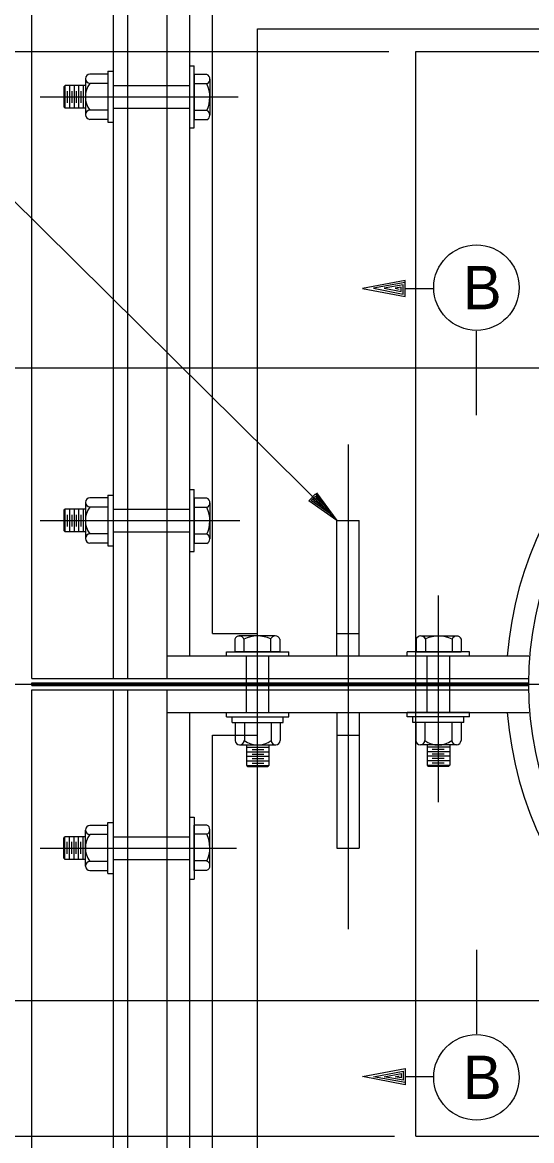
# Model space of a CAD drawing. Extents: x 22369.6 to 22389.4, y 22369.6 to 22386.
# Drawn here: x 22372.155 to 22373.095, y 22377.472 to 22379.534 of the extents above; entities that cross this region are included whole.
import ezdxf

# ---------------------------------------------------------------- set-up
doc = ezdxf.new("R2010")
doc.units = 0
for name, color, linetype in [('Level 1', 7, 'Continuous'), ('Level 2', 7, 'Continuous'), ('Level 3', 7, 'Continuous')]:
    doc.layers.add(name, color=color, linetype=linetype)

msp = doc.modelspace()

# ---------------------------------------------------------------- linework, layer by layer
at = {"layer": 'Level 1'}
for p, q in [((22370.551, 22379.4805), (22372.831, 22379.4805)), ((22372.4643, 22379.4545), (22372.4721, 22379.4545)), ((22372.4721, 22379.3399), (22372.4721, 22379.4545)), ((22372.3132, 22379.4389), (22372.28, 22379.4389)), ((22372.3132, 22379.4441), (22372.3132, 22379.3503)), ((22372.3132, 22379.4441), (22372.3237, 22379.4441)), ((22372.4721, 22379.4382), (22372.4721, 22379.3549)), ((22372.4956, 22379.4382), (22372.4721, 22379.4382)), ((22372.2341, 22379.418), (22372.232, 22379.4158)), ((22372.232, 22379.4158), (22372.232, 22379.3785)), ((22372.234, 22379.418), (22372.234, 22379.3764)), ((22372.2716, 22379.418), (22372.2341, 22379.418)), ((22372.2424, 22379.418), (22372.2424, 22379.3764)), ((22372.2507, 22379.418), (22372.2507, 22379.3764)), ((22372.259, 22379.418), (22372.259, 22379.3764)), ((22372.2674, 22379.418), (22372.2674, 22379.3764)), ((22372.2716, 22379.4304), (22372.2716, 22379.3639)), ((22372.3132, 22379.4217), (22372.28, 22379.4217)), ((22372.3237, 22379.418), (22372.4643, 22379.418)), ((22372.4958, 22379.421), (22372.4721, 22379.421)), ((22372.5012, 22379.4297), (22372.5012, 22379.3633)), ((22372.188, 22379.3972), (22372.5534, 22379.3972)), ((22372.2382, 22379.4076), (22372.2382, 22379.3858)), ((22372.2465, 22379.4076), (22372.2465, 22379.3858)), ((22372.2549, 22379.4076), (22372.2549, 22379.3858)), ((22372.2632, 22379.4076), (22372.2632, 22379.3858)), ((22372.2343, 22379.3764), (22372.232, 22379.3785)), ((22372.2716, 22379.3764), (22372.2343, 22379.3764)), ((22372.3132, 22379.3724), (22372.28, 22379.3724)), ((22372.3237, 22379.3764), (22372.4643, 22379.3764)), ((22372.4957, 22379.3717), (22372.4721, 22379.3717)), ((22372.3132, 22379.3555), (22372.28, 22379.3555)), ((22372.28, 22379.3555), (22372.28, 22379.3555)), ((22372.3132, 22379.3503), (22372.3237, 22379.3503)), ((22372.4956, 22379.3549), (22372.4721, 22379.3549)), ((22372.4643, 22379.3399), (22372.4721, 22379.3399)), ((22370.7204, 22378.8972), (22373.7143, 22378.8972)), ((22372.756, 22378.7557), (22372.756, 22377.8621)), ((22372.4643, 22378.6732), (22372.4721, 22378.6732)), ((22372.4721, 22378.5587), (22372.4721, 22378.6732)), ((22372.2716, 22378.6491), (22372.2716, 22378.5827)), ((22372.3132, 22378.6576), (22372.28, 22378.6576)), ((22372.3132, 22378.6628), (22372.3132, 22378.5691)), ((22372.3132, 22378.6628), (22372.3237, 22378.6628)), ((22372.4721, 22378.657), (22372.4721, 22378.5737)), ((22372.4956, 22378.657), (22372.4721, 22378.657)), ((22372.5012, 22378.6485), (22372.5012, 22378.582)), ((22372.2341, 22378.6368), (22372.232, 22378.6346)), ((22372.232, 22378.6346), (22372.232, 22378.5972)), ((22372.234, 22378.6368), (22372.234, 22378.5951)), ((22372.2716, 22378.6368), (22372.2341, 22378.6368)), ((22372.2424, 22378.6368), (22372.2424, 22378.5951)), ((22372.2507, 22378.6368), (22372.2507, 22378.5951)), ((22372.259, 22378.6368), (22372.259, 22378.5951)), ((22372.2674, 22378.6368), (22372.2674, 22378.5951)), ((22372.3132, 22378.6404), (22372.28, 22378.6404)), ((22372.3237, 22378.6368), (22372.4643, 22378.6368)), ((22372.4958, 22378.6398), (22372.4721, 22378.6398)), ((22372.188, 22378.616), (22372.5565, 22378.616)), ((22372.2382, 22378.6263), (22372.2382, 22378.6045)), ((22372.2465, 22378.6263), (22372.2465, 22378.6045)), ((22372.2549, 22378.6263), (22372.2549, 22378.6045)), ((22372.2632, 22378.6263), (22372.2632, 22378.6045)), ((22372.2343, 22378.5951), (22372.232, 22378.5972)), ((22372.2716, 22378.5951), (22372.2343, 22378.5951)), ((22372.3132, 22378.5911), (22372.28, 22378.5911)), ((22372.3237, 22378.5951), (22372.4643, 22378.5951)), ((22372.4957, 22378.5905), (22372.4721, 22378.5905)), ((22372.3132, 22378.5743), (22372.28, 22378.5743)), ((22372.28, 22378.5743), (22372.28, 22378.5743)), ((22372.3132, 22378.5691), (22372.3237, 22378.5691)), ((22372.4956, 22378.5737), (22372.4721, 22378.5737)), ((22372.4643, 22378.5587), (22372.4721, 22378.5587)), ((22372.5893, 22378.0966), (22372.5893, 22378.4775)), ((22372.9226, 22378.0966), (22372.9226, 22378.4775)), ((22372.6218, 22378.4029), (22372.5554, 22378.4029)), ((22372.8901, 22378.4029), (22372.9566, 22378.4029)), ((22372.547, 22378.3973), (22372.547, 22378.3738)), ((22372.5638, 22378.3974), (22372.5638, 22378.3738)), ((22372.6131, 22378.3975), (22372.6131, 22378.3738)), ((22372.6303, 22378.3973), (22372.6303, 22378.3738)), ((22372.8816, 22378.3973), (22372.8816, 22378.3738)), ((22372.8988, 22378.3975), (22372.8988, 22378.3738)), ((22372.9481, 22378.3974), (22372.9481, 22378.3738)), ((22372.9649, 22378.3973), (22372.9649, 22378.3738)), ((22372.532, 22378.3738), (22372.6466, 22378.3738)), ((22372.532, 22378.366), (22372.532, 22378.3738)), ((22372.6303, 22378.3738), (22372.547, 22378.3738)), ((22372.5685, 22378.2618), (22372.5685, 22378.366)), ((22372.6101, 22378.2618), (22372.6101, 22378.366)), ((22372.6466, 22378.366), (22372.6466, 22378.3738)), ((22372.9799, 22378.3738), (22372.8653, 22378.3738)), ((22372.8653, 22378.366), (22372.8653, 22378.3738)), ((22372.8816, 22378.3738), (22372.9649, 22378.3738)), ((22372.9018, 22378.2618), (22372.9018, 22378.366)), ((22372.9435, 22378.2618), (22372.9435, 22378.366)), ((22372.9799, 22378.366), (22372.9799, 22378.3738)), ((22371.1298, 22378.3139), (22373.7143, 22378.3139)), ((22372.1726, 22378.3165), (22373.0893, 22378.3165)), ((22372.1726, 22378.3113), (22372.1726, 22378.3165)), ((22372.1726, 22378.3113), (22373.0893, 22378.3113)), ((22372.532, 22378.254), (22372.532, 22378.2618)), ((22372.532, 22378.2618), (22372.6466, 22378.2618)), ((22372.6466, 22378.254), (22372.6466, 22378.2618)), ((22372.8653, 22378.254), (22372.8653, 22378.2618)), ((22372.9799, 22378.2618), (22372.8653, 22378.2618)), ((22372.9799, 22378.254), (22372.9799, 22378.2618)), ((22372.532, 22378.254), (22372.6466, 22378.254)), ((22372.5424, 22378.2436), (22372.5424, 22378.254)), ((22372.5424, 22378.2436), (22372.6362, 22378.2436)), ((22372.5476, 22378.2436), (22372.5476, 22378.2103)), ((22372.5648, 22378.2436), (22372.5648, 22378.2103)), ((22372.6141, 22378.2436), (22372.6141, 22378.2103)), ((22372.631, 22378.2436), (22372.631, 22378.2103)), ((22372.6362, 22378.2436), (22372.6362, 22378.254)), ((22372.9799, 22378.254), (22372.8653, 22378.254)), ((22372.8757, 22378.2436), (22372.8757, 22378.254)), ((22372.9695, 22378.2436), (22372.8757, 22378.2436)), ((22372.881, 22378.2436), (22372.881, 22378.2103)), ((22372.8978, 22378.2436), (22372.8978, 22378.2103)), ((22372.9471, 22378.2436), (22372.9471, 22378.2103)), ((22372.9643, 22378.2436), (22372.9643, 22378.2103)), ((22372.9695, 22378.2436), (22372.9695, 22378.254)), ((22372.5561, 22378.2019), (22372.6226, 22378.2019)), ((22372.5685, 22378.2019), (22372.5685, 22378.1644)), ((22372.5685, 22378.1977), (22372.6101, 22378.1977)), ((22372.6101, 22378.2019), (22372.6101, 22378.1646)), ((22372.631, 22378.2103), (22372.631, 22378.2103)), ((22372.881, 22378.2103), (22372.881, 22378.2103)), ((22372.9558, 22378.2019), (22372.8894, 22378.2019)), ((22372.9018, 22378.2019), (22372.9018, 22378.1646)), ((22372.9435, 22378.1977), (22372.9018, 22378.1977)), ((22372.9435, 22378.2019), (22372.9435, 22378.1644)), ((22372.5685, 22378.1893), (22372.6101, 22378.1893)), ((22372.5685, 22378.181), (22372.6101, 22378.181)), ((22372.5789, 22378.1935), (22372.6007, 22378.1935)), ((22372.5789, 22378.1852), (22372.6007, 22378.1852)), ((22372.5789, 22378.1768), (22372.6007, 22378.1768)), ((22372.9435, 22378.1893), (22372.9018, 22378.1893)), ((22372.9435, 22378.181), (22372.9018, 22378.181)), ((22372.933, 22378.1935), (22372.9112, 22378.1935)), ((22372.933, 22378.1852), (22372.9112, 22378.1852)), ((22372.933, 22378.1768), (22372.9112, 22378.1768)), ((22372.5685, 22378.1727), (22372.6101, 22378.1727)), ((22372.5685, 22378.1644), (22372.5707, 22378.1623)), ((22372.5685, 22378.1643), (22372.6101, 22378.1643)), ((22372.5707, 22378.1623), (22372.608, 22378.1623)), ((22372.5789, 22378.1685), (22372.6007, 22378.1685)), ((22372.6101, 22378.1646), (22372.608, 22378.1623)), ((22372.9435, 22378.1727), (22372.9018, 22378.1727)), ((22372.9018, 22378.1646), (22372.9039, 22378.1623)), ((22372.9435, 22378.1643), (22372.9018, 22378.1643)), ((22372.9412, 22378.1623), (22372.9039, 22378.1623)), ((22372.933, 22378.1685), (22372.9112, 22378.1685)), ((22372.9435, 22378.1644), (22372.9412, 22378.1623)), ((22372.3132, 22378.0535), (22372.28, 22378.0535)), ((22372.28, 22378.0535), (22372.28, 22378.0535)), ((22372.3132, 22377.9649), (22372.3132, 22378.0587)), ((22372.3132, 22378.0587), (22372.3237, 22378.0587)), ((22372.4643, 22378.0691), (22372.4721, 22378.0691)), ((22372.4721, 22378.0691), (22372.4721, 22377.9545)), ((22372.4721, 22377.9707), (22372.4721, 22378.0541)), ((22372.4956, 22378.0541), (22372.4721, 22378.0541)), ((22372.2343, 22378.0326), (22372.232, 22378.0305)), ((22372.232, 22377.9932), (22372.232, 22378.0305)), ((22372.234, 22377.991), (22372.234, 22378.0326)), ((22372.2716, 22378.0326), (22372.2343, 22378.0326)), ((22372.2424, 22377.991), (22372.2424, 22378.0326)), ((22372.2507, 22377.991), (22372.2507, 22378.0326)), ((22372.259, 22377.991), (22372.259, 22378.0326)), ((22372.2674, 22377.991), (22372.2674, 22378.0326)), ((22372.2716, 22377.9786), (22372.2716, 22378.0451)), ((22372.3132, 22378.0366), (22372.28, 22378.0366)), ((22372.3237, 22378.0326), (22372.4643, 22378.0326)), ((22372.4957, 22378.0372), (22372.4721, 22378.0372)), ((22372.5012, 22377.9792), (22372.5012, 22378.0457)), ((22372.188, 22378.0118), (22372.5503, 22378.0118)), ((22372.2382, 22378.0014), (22372.2382, 22378.0232)), ((22372.2465, 22378.0014), (22372.2465, 22378.0232)), ((22372.2549, 22378.0014), (22372.2549, 22378.0232)), ((22372.2632, 22378.0014), (22372.2632, 22378.0232)), ((22372.2341, 22377.991), (22372.232, 22377.9932)), ((22372.2716, 22377.991), (22372.2341, 22377.991)), ((22372.3237, 22377.991), (22372.4643, 22377.991)), ((22372.4958, 22377.988), (22372.4721, 22377.988)), ((22372.3132, 22377.9873), (22372.28, 22377.9873)), ((22372.3132, 22377.9701), (22372.28, 22377.9701)), ((22372.4956, 22377.9707), (22372.4721, 22377.9707)), ((22372.3132, 22377.9649), (22372.3237, 22377.9649)), ((22372.4643, 22377.9545), (22372.4721, 22377.9545)), ((22370.7138, 22377.7305), (22373.7143, 22377.7305)), ((22370.5477, 22377.4805), (22372.8415, 22377.4805))]:
    msp.add_line(p, q, dxfattribs=at)
for centre, radius, start, end in [((22372.2801, 22379.4304), 0.00844, 90.5659, 269.4341), ((22372.4919, 22379.4296), 0.00938, 294.0009, 66.8325), ((22372.3122, 22379.397), 0.0406, 142.4343, 217.5657), ((22372.4443, 22379.3966), 0.0569, 334.116, 25.4481), ((22372.2801, 22379.364), 0.00843, 90.4975, 269.5025), ((22372.4921, 22379.3633), 0.00912, 292.8005, 67.625), ((22372.2801, 22378.6492), 0.00844, 90.5659, 269.4341), ((22372.4919, 22378.6484), 0.00938, 294.0009, 66.8325), ((22372.3122, 22378.6158), 0.0406, 142.4343, 217.5657), ((22372.4443, 22378.6153), 0.0569, 334.116, 25.4481), ((22372.2801, 22378.5827), 0.00843, 90.4975, 269.5025), ((22372.4921, 22378.5821), 0.00912, 292.8005, 67.625), ((22372.5554, 22378.3937), 0.00912, 22.375, 157.1995), ((22372.5887, 22378.346), 0.0569, 64.5519, 115.884), ((22372.6217, 22378.3936), 0.00938, 23.1675, 155.9991), ((22372.8902, 22378.3936), 0.00938, 24.0009, 156.8325), ((22372.9232, 22378.346), 0.0569, 64.116, 115.4481), ((22372.9565, 22378.3937), 0.00912, 22.8005, 157.625), ((22372.5561, 22378.2104), 0.00844, 180.5659, 359.4341), ((22372.5895, 22378.2425), 0.0406, 232.4343, 307.5657), ((22372.6225, 22378.2104), 0.00843, 180.4975, 359.5025), ((22372.8894, 22378.2104), 0.00843, 180.4975, 359.5025), ((22372.9224, 22378.2425), 0.0406, 232.4343, 307.5657), ((22372.9559, 22378.2104), 0.00844, 180.5659, 359.4341), ((22372.2801, 22378.045), 0.00843, 90.4975, 269.5025), ((22372.4921, 22378.0457), 0.00912, 292.375, 67.1995), ((22372.3122, 22378.012), 0.0406, 142.4343, 217.5657), ((22372.4443, 22378.0124), 0.0569, 334.5519, 25.884), ((22372.4919, 22377.9794), 0.00938, 293.1675, 65.9991), ((22372.2801, 22377.9786), 0.00844, 90.5659, 269.4341)]:
    msp.add_arc(centre, radius, start, end, dxfattribs=at)
at = {"layer": 'Level 2'}
for p, q in [((22372.1726, 22378.3243), (22372.1726, 22379.9389)), ((22372.3497, 22378.3243), (22372.3497, 22379.7878)), ((22372.3237, 22378.3243), (22372.3237, 22379.7618)), ((22372.4226, 22378.3243), (22372.4226, 22379.6889)), ((22372.4643, 22378.366), (22372.4643, 22379.6472)), ((22372.506, 22378.4076), (22372.506, 22379.6055)), ((22372.5893, 22378.4076), (22372.5893, 22379.5222)), ((22372.5893, 22379.5222), (22374.8393, 22379.5222)), ((22372.881, 22377.4805), (22372.881, 22379.4805)), ((22372.881, 22379.4805), (22374.5476, 22379.4805)), ((22372.7228, 22378.6281), (22372.7228, 22378.6281)), ((22372.7351, 22378.616), (22372.7768, 22378.616)), ((22372.7351, 22378.366), (22372.7351, 22378.616)), ((22372.7351, 22378.616), (22372.7351, 22378.616)), ((22372.7768, 22378.366), (22372.7768, 22378.616)), ((22372.506, 22378.4076), (22372.5893, 22378.4076)), ((22372.7351, 22378.4076), (22372.7768, 22378.4076)), ((22372.4226, 22378.366), (22373.0894, 22378.366)), ((22372.1726, 22378.3243), (22373.0894, 22378.3243)), ((22372.1726, 22378.3035), (22373.0894, 22378.3035)), ((22372.1726, 22376.6889), (22372.1726, 22378.3035)), ((22372.3237, 22376.866), (22372.3237, 22378.3035)), ((22372.3497, 22376.8399), (22372.3497, 22378.3035)), ((22372.4226, 22376.9389), (22372.4226, 22378.3035)), ((22372.4226, 22378.2618), (22373.0894, 22378.2618)), ((22372.4643, 22376.9805), (22372.4643, 22378.2618)), ((22372.7351, 22378.2618), (22372.7351, 22378.0118)), ((22372.7768, 22378.2618), (22372.7768, 22378.0118)), ((22372.506, 22377.0222), (22372.506, 22378.2201)), ((22372.506, 22378.2201), (22372.5893, 22378.2201)), ((22372.5893, 22377.1055), (22372.5893, 22378.2201)), ((22372.7351, 22378.2201), (22372.7768, 22378.2201)), ((22372.7351, 22378.0118), (22372.7768, 22378.0118)), ((22372.881, 22377.4805), (22374.5476, 22377.4805))]:
    msp.add_line(p, q, dxfattribs=at)
for points in [[(22371.924, 22379.2735), (22372.0705, 22379.2735), (22372.7351, 22378.616)], [(22372.6981, 22378.6671), (22372.7351, 22378.616), (22372.6835, 22378.6524), (22372.696, 22378.665), (22372.7228, 22378.6281), (22372.6878, 22378.6529), (22372.6958, 22378.661), (22372.711, 22378.6399), (22372.692, 22378.6534), (22372.6953, 22378.6568), (22372.6986, 22378.6521)]]:
    msp.add_lwpolyline(points, dxfattribs=at)
msp.add_circle((22373.7143, 22378.3139), 0.625, dxfattribs=at)
for start, end in [(4.4808, 175.5192), (184.4808, 355.5192)]:
    msp.add_arc((22373.7143, 22378.3139), 0.6667, start, end, dxfattribs=at)
at = {"layer": 'Level 3'}
for p, q in [((22372.8616, 22379.0438), (22372.9141, 22379.0438)), ((22372.9928, 22378.8103), (22372.9928, 22378.9651)), ((22372.9928, 22377.824), (22372.9928, 22377.6691)), ((22372.8616, 22377.5905), (22372.9141, 22377.5905))]:
    msp.add_line(p, q, dxfattribs=at)
for points in [[(22372.8616, 22379.0548), (22372.8616, 22379.0587), (22372.7828, 22379.0438), (22372.8616, 22379.0291), (22372.8616, 22379.0548), (22372.8029, 22379.044), (22372.8578, 22379.0335), (22372.8578, 22379.0505), (22372.8227, 22379.044), (22372.8541, 22379.0381), (22372.8541, 22379.046), (22372.8428, 22379.044), (22372.8503, 22379.0426)], [(22372.8616, 22377.5794), (22372.8616, 22377.5755), (22372.7828, 22377.5905), (22372.8616, 22377.6052), (22372.8616, 22377.5794), (22372.8029, 22377.5902), (22372.8578, 22377.6007), (22372.8578, 22377.5838), (22372.8227, 22377.5902), (22372.8541, 22377.5961), (22372.8541, 22377.5882), (22372.8428, 22377.5902), (22372.8503, 22377.5916)]]:
    msp.add_lwpolyline(points, dxfattribs=at)
for centre in [(22372.9928, 22379.0453), (22372.9928, 22377.589)]:
    msp.add_circle(centre, 0.0788, dxfattribs=at)

# ---------------------------------------------------------------- texts
for p in [(22372.9679, 22379.0053), (22372.9679, 22377.549)]:
    msp.add_text('B', height=0.08, dxfattribs=at).set_placement(p)

doc.saveas('drawing.dxf')
